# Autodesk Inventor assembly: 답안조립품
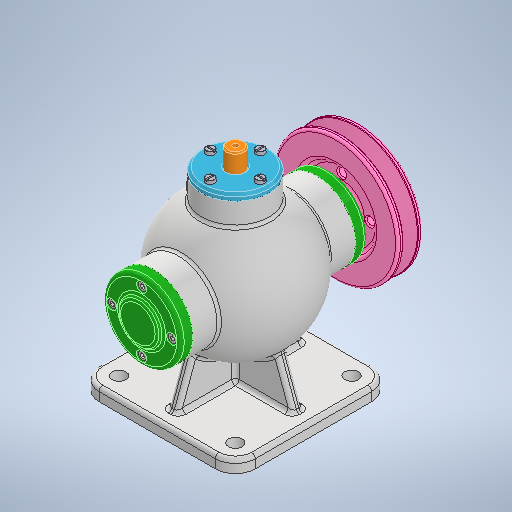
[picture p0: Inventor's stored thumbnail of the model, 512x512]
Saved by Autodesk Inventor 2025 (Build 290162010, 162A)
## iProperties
Created: 2024-07
Part Number: 답안조립품
Document SubType Name: Assembly
Designer: Admin
Author: Admin
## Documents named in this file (15)
- C:\Users\Admin\Desktop\740708V1010\답안조립품.iam
- C:\Users\Admin\Desktop\740708V1010\본체.ipt
- C:\Users\Admin\Desktop\740708V1010\슬라이드\슬라이드.ipt
- C:\Users\Admin\Desktop\740708V1010\앞커버\앞커버.ipt
- C:\Users\Admin\Desktop\740708V1010\오일실 15 30 7\오일실 15 30 7.ipt
- C:\Users\Admin\Desktop\740708V1010\칼라\칼라.ipt
- C:\Users\Admin\Desktop\740708V1010\키 4 x 4 x 12\키 4 x 4 x 12.ipt
- C:\Users\Admin\Desktop\740708V1010\편심축\편심축.ipt
- C:\Users\Admin\Desktop\740708V1010\V-벨트풀리\V-벨트풀리.ipt
- C:\Users\Admin\Desktop\740708V1010\너트 M8\너트 M8.ipt
- C:\Users\Admin\Desktop\740708V1010\뒤커버\뒤커버.ipt
- C:\Users\Admin\Desktop\740708V1010\베어링- 6202\베어링- 6202.ipt
- C:\Users\Admin\Desktop\740708V1010\볼트 M4 x 12\볼트 M4 x 12.ipt
- C:\Users\Admin\Desktop\740708V1010\볼트 M4 x 16\볼트 M4 x 16.ipt
- C:\Users\Admin\Desktop\740708V1010\상부커버\상부커버.ipt
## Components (1 placed, 1 different names)
1. V-벨트풀리:1 — 각도:5
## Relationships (1: Angle 1)
- 각도:5 [Angle]: V-벨트풀리:1
